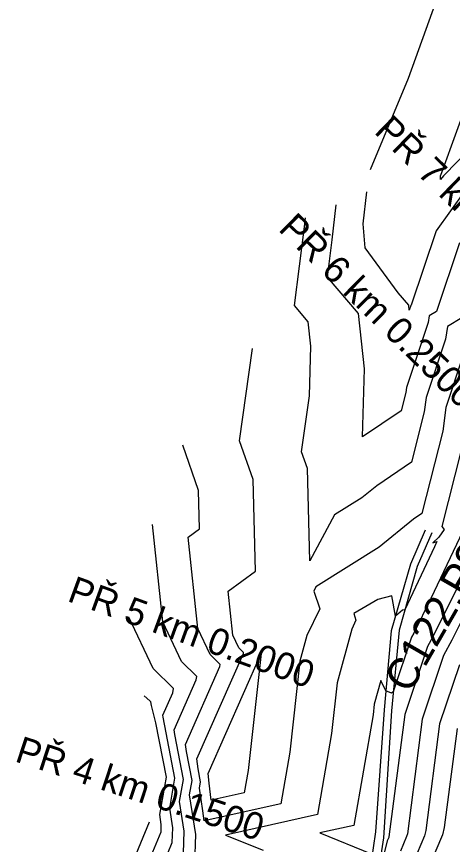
# Model space of a CAD drawing. Extents: x -549394 to -546608, y -1037055 to -1033629.
# Drawn here: x -548903.2 to -548756.1, y -1034201.2 to -1033921.5 of the extents above; entities that cross this region are included whole.
import ezdxf

# ---------------------------------------------------------------- set-up
doc = ezdxf.new("R2010")
doc.units = 0
for name, color, linetype in [('hlavni_vrst', 7, 'Continuous'), ('hrana_L', 7, 'Continuous'), ('norm_vrst', 7, 'Continuous'), ('x_popis_pricne_rezy_C122', 7, 'Continuous'), ('x_popis_velky_C122', 7, 'Continuous')]:
    doc.layers.add(name, color=color, linetype=linetype)

msp = doc.modelspace()

# ---------------------------------------------------------------- linework, layer by layer
at = {"layer": 'hlavni_vrst'}
for p, q in [((-548827.91, -1034064.82), (-548823.56, -1034033.65)), ((-548752.53, -1034036.21), (-548758.32, -1034053.57)), ((-548758.32, -1034053.57), (-548759.35, -1034061.54)), ((-548759.35, -1034061.54), (-548766.36, -1034089.43)), ((-548823.39, -1034077.91), (-548827.91, -1034064.82)), ((-548822.61, -1034108.85), (-548823.39, -1034077.91)), ((-548766.36, -1034089.43), (-548769.21, -1034091.35)), ((-548769.21, -1034091.35), (-548780.77, -1034100.82)), ((-548780.77, -1034100.82), (-548802.13, -1034114.16)), ((-548831.8, -1034115.63), (-548822.61, -1034108.85)), ((-548802.13, -1034114.16), (-548802.91, -1034115.6)), ((-548830.24, -1034130.51), (-548831.8, -1034115.63)), ((-548802.91, -1034115.6), (-548800.87, -1034121.57)), ((-548800.87, -1034121.57), (-548805.2, -1034130.59)), ((-548828.23, -1034134.75), (-548830.24, -1034130.51)), ((-548805.2, -1034130.59), (-548807.58, -1034139.32)), ((-548842.4, -1034172.34), (-548826.65, -1034136.72)), ((-548826.6, -1034136.36), (-548828.23, -1034134.75)), ((-548826.65, -1034136.72), (-548826.6, -1034136.36)), ((-548807.58, -1034139.32), (-548810.97, -1034169.99)), ((-548753.73, -1034140.48), (-548760.4, -1034160.49)), ((-548760.4, -1034160.49), (-548765.06, -1034196.56)), ((-548810.97, -1034169.99), (-548813.99, -1034187.47)), ((-548841.96, -1034175.65), (-548842.4, -1034172.34)), ((-548841.11, -1034180.08), (-548841.96, -1034175.65)), ((-548841.49, -1034182.24), (-548841.11, -1034180.08)), ((-548840.29, -1034189.9), (-548841.49, -1034182.24)), ((-548813.99, -1034187.47), (-548839.92, -1034193.24)), ((-548839.92, -1034193.24), (-548840.29, -1034189.9)), ((-548866.32, -1034212.87), (-548858.35, -1034193.59)), ((-548765.47, -1034198.27), (-548769.17, -1034207.05)), ((-548765.06, -1034196.56), (-548765.47, -1034198.27))]:
    msp.add_line(p, q, dxfattribs=at)
at = {"layer": 'hrana_L'}
for p, q in [((-548765.24, -1034094.98), (-548770.17, -1034106.46)), ((-548763, -1034095.87), (-548768.02, -1034107.25)), ((-548770.17, -1034106.46), (-548776.76, -1034129.09)), ((-548768.02, -1034107.25), (-548774.07, -1034128.86)), ((-548776.76, -1034129.09), (-548779.07, -1034155.75)), ((-548774.07, -1034128.86), (-548776.65, -1034156.06)), ((-548779.07, -1034155.75), (-548782.05, -1034196.95)), ((-548776.65, -1034156.06), (-548779.39, -1034199)), ((-548782.05, -1034196.95), (-548784.21, -1034211.37)), ((-548779.39, -1034199), (-548781.43, -1034212.74))]:
    msp.add_line(p, q, dxfattribs=at)
at = {"layer": 'norm_vrst'}
for p, q in [((-548770.93, -1033942.25), (-548761.43, -1033916.07)), ((-548759.67, -1033974.12), (-548741.85, -1033924.97)), ((-548722.73, -1033938.1), (-548759.11, -1033975.23)), ((-548783.78, -1033973.1), (-548770.93, -1033942.25)), ((-548760.14, -1033975.25), (-548759.67, -1033974.12)), ((-548760.04, -1033976.54), (-548760.14, -1033975.25)), ((-548759.11, -1033975.23), (-548760.04, -1033976.54)), ((-548751.9, -1033980.31), (-548761.58, -1033993.91)), ((-548786.2, -1033991.45), (-548785.02, -1033980.7)), ((-548796.62, -1033996.93), (-548795.32, -1033985.1)), ((-548805.97, -1033992.57), (-548805.63, -1033989.5)), ((-548785.58, -1033999.63), (-548786.2, -1033991.45)), ((-548809.39, -1034019.11), (-548805.97, -1033992.57)), ((-548761.58, -1033993.91), (-548770.05, -1034019.02)), ((-548798.24, -1034009.5), (-548796.62, -1033996.93)), ((-548774.44, -1034014.78), (-548785.58, -1033999.63)), ((-548753.63, -1033997.94), (-548761.45, -1034021.12)), ((-548787.78, -1034021.81), (-548798.24, -1034009.5)), ((-548770.82, -1034019.04), (-548774.44, -1034014.78)), ((-548804.74, -1034024.58), (-548809.39, -1034019.11)), ((-548770.64, -1034020.65), (-548770.82, -1034019.04)), ((-548770.13, -1034019.13), (-548770.64, -1034020.65)), ((-548770.12, -1034019.07), (-548770.13, -1034019.13)), ((-548770.05, -1034019.02), (-548770.12, -1034019.07)), ((-548785.7, -1034040.5), (-548787.78, -1034021.81)), ((-548761.45, -1034021.12), (-548763.92, -1034022.61)), ((-548803.82, -1034032.89), (-548804.74, -1034024.58)), ((-548764.27, -1034024.82), (-548771.59, -1034046.78)), ((-548763.92, -1034022.61), (-548764.27, -1034024.82)), ((-548752.84, -1034023.23), (-548757.71, -1034026.15)), ((-548757.71, -1034026.15), (-548758.4, -1034030.52)), ((-548758.4, -1034030.52), (-548764.96, -1034050.17)), ((-548804.34, -1034049.67), (-548803.82, -1034032.89)), ((-548786.42, -1034063.53), (-548785.7, -1034040.5)), ((-548771.59, -1034046.78), (-548771.82, -1034048.54)), ((-548806.98, -1034068.56), (-548804.34, -1034049.67)), ((-548771.82, -1034048.54), (-548773.37, -1034054.73)), ((-548764.96, -1034050.17), (-548765.58, -1034055.04)), ((-548773.37, -1034054.73), (-548786.42, -1034063.53)), ((-548765.58, -1034055.04), (-548769.87, -1034072.08)), ((-548841.76, -1034081.61), (-548847.06, -1034066.26)), ((-548805.03, -1034074.21), (-548806.98, -1034068.56)), ((-548753.11, -1034068.04), (-548759.59, -1034093.8)), ((-548769.87, -1034072.08), (-548781.63, -1034080.02)), ((-548804.23, -1034105.43), (-548805.03, -1034074.21)), ((-548781.63, -1034080.02), (-548786.62, -1034084.1)), ((-548841.43, -1034094.56), (-548841.76, -1034081.61)), ((-548786.62, -1034084.1), (-548795.84, -1034089.86)), ((-548795.84, -1034089.86), (-548804.23, -1034105.43)), ((-548735.41, -1034090.19), (-548756.29, -1034132.24)), ((-548853.84, -1034126.05), (-548857.3, -1034093.07)), ((-548845.27, -1034097.4), (-548841.43, -1034094.56)), ((-548758.88, -1034094.82), (-548760.61, -1034097.41)), ((-548759.59, -1034093.8), (-548758.88, -1034094.82)), ((-548842.04, -1034128.28), (-548845.27, -1034097.4)), ((-548752.55, -1034095.38), (-548763.32, -1034118.11)), ((-548760.62, -1034097.41), (-548762.66, -1034099.32)), ((-548760.62, -1034097.41), (-548760.61, -1034097.41)), ((-548762.09, -1034100.69), (-548772.14, -1034121.96)), ((-548762.66, -1034099.32), (-548761.36, -1034098.81)), ((-548762.66, -1034099.32), (-548762.66, -1034099.32)), ((-548761.36, -1034098.81), (-548762.09, -1034100.69)), ((-548761.36, -1034098.81), (-548761.36, -1034098.81)), ((-548749.37, -1034104.15), (-548762.71, -1034131.02)), ((-548776.52, -1034117.22), (-548781.24, -1034118.42)), ((-548775.31, -1034124.1), (-548776.52, -1034117.22)), ((-548781.24, -1034118.42), (-548789.39, -1034123.23)), ((-548763.32, -1034118.11), (-548769.13, -1034129.8)), ((-548789.39, -1034123.23), (-548788.64, -1034125.44)), ((-548772.89, -1034122.08), (-548775.31, -1034124.1)), ((-548772.14, -1034121.96), (-548772.89, -1034122.08)), ((-548857.15, -1034141.72), (-548865.38, -1034124.38)), ((-548788.64, -1034125.44), (-548790.08, -1034128.44)), ((-548847.51, -1034139.4), (-548853.84, -1034126.05)), ((-548837.87, -1034137.08), (-548842.04, -1034128.28)), ((-548790.08, -1034128.44), (-548795.02, -1034146.56)), ((-548769.92, -1034131.23), (-548776.04, -1034149.6)), ((-548769.13, -1034129.8), (-548769.92, -1034131.23)), ((-548762.71, -1034131.02), (-548764.52, -1034134.32)), ((-548764.52, -1034134.32), (-548772.18, -1034157.28)), ((-548756.29, -1034132.24), (-548759.13, -1034137.4)), ((-548838.59, -1034177.28), (-548820.65, -1034136.68)), ((-548834.48, -1034140.42), (-548837.87, -1034137.08)), ((-548820.65, -1034136.68), (-548825.02, -1034176.26)), ((-548842.37, -1034144.47), (-548847.51, -1034139.4)), ((-548759.13, -1034137.4), (-548766.29, -1034158.88)), ((-548850.26, -1034148.53), (-548857.15, -1034141.72)), ((-548846.21, -1034167.4), (-548834.61, -1034141.15)), ((-548834.61, -1034141.15), (-548834.48, -1034140.42)), ((-548850.02, -1034162.46), (-548842.56, -1034145.59)), ((-548842.56, -1034145.59), (-548842.37, -1034144.47)), ((-548795.02, -1034146.56), (-548796.92, -1034163.72)), ((-548780.28, -1034145.8), (-548782.46, -1034153.8)), ((-548778.51, -1034149.32), (-548780.28, -1034145.8)), ((-548858.19, -1034152.69), (-548860.15, -1034151.05)), ((-548853.82, -1034157.52), (-548850.51, -1034150.02)), ((-548850.51, -1034150.02), (-548850.26, -1034148.53)), ((-548776.67, -1034150.12), (-548778.51, -1034149.32)), ((-548776.04, -1034149.6), (-548776.67, -1034150.12)), ((-548858.19, -1034152.69), (-548857.94, -1034153.02)), ((-548857.7, -1034154.26), (-548857.94, -1034153.02)), ((-548782.46, -1034153.8), (-548782.86, -1034157.44)), ((-548856.17, -1034160.15), (-548857.7, -1034154.26)), ((-548853.73, -1034158.22), (-548853.82, -1034157.52)), ((-548849.76, -1034178.87), (-548853.73, -1034158.22)), ((-548782.86, -1034157.44), (-548789.33, -1034194.79)), ((-548772.18, -1034157.28), (-548777.52, -1034198.68)), ((-548766.29, -1034158.88), (-548771.29, -1034197.62)), ((-548852.64, -1034178.46), (-548856.17, -1034160.15)), ((-548754.51, -1034162.09), (-548758.83, -1034195.5)), ((-548849.81, -1034164.03), (-548850.02, -1034162.46)), ((-548846.87, -1034179.27), (-548849.81, -1034164.03)), ((-548796.92, -1034163.72), (-548801.66, -1034191.13)), ((-548845.88, -1034169.84), (-548846.21, -1034167.4)), ((-548843.99, -1034179.67), (-548845.88, -1034169.84)), ((-548825.02, -1034176.26), (-548826.33, -1034183.81)), ((-548854.88, -1034191.15), (-548852.64, -1034178.46)), ((-548851.53, -1034188.92), (-548849.76, -1034178.87)), ((-548838.16, -1034180.53), (-548838.59, -1034177.28)), ((-548848.19, -1034186.7), (-548846.87, -1034179.27)), ((-548844.84, -1034184.47), (-548843.99, -1034179.67)), ((-548837.52, -1034186.3), (-548838.16, -1034180.53)), ((-548842.74, -1034197.92), (-548844.84, -1034184.47)), ((-548826.33, -1034183.81), (-548837.52, -1034186.3)), ((-548846.61, -1034196.78), (-548848.19, -1034186.7)), ((-548850.49, -1034195.63), (-548851.53, -1034188.92)), ((-548854.36, -1034194.49), (-548854.88, -1034191.15)), ((-548801.66, -1034191.13), (-548832.73, -1034198.05)), ((-548854.44, -1034196.95), (-548854.36, -1034194.49)), ((-548850.64, -1034200.57), (-548850.49, -1034195.63)), ((-548789.33, -1034194.79), (-548800.85, -1034197.36)), ((-548758.83, -1034195.5), (-548759.42, -1034197.95)), ((-548860.59, -1034211.8), (-548854.44, -1034196.95)), ((-548846.84, -1034204.2), (-548846.61, -1034196.78)), ((-548843.05, -1034207.82), (-548842.74, -1034197.92)), ((-548832.73, -1034198.05), (-548819.92, -1034203.21)), ((-548800.85, -1034197.36), (-548783.18, -1034204.48)), ((-548777.52, -1034198.68), (-548777.57, -1034198.9)), ((-548771.52, -1034198.59), (-548773.61, -1034203.55)), ((-548771.29, -1034197.62), (-548771.52, -1034198.59)), ((-548759.42, -1034197.95), (-548764.73, -1034210.55)), ((-548854.85, -1034210.74), (-548850.64, -1034200.57)), ((-548778.06, -1034200.05), (-548781.29, -1034212.82)), ((-548777.57, -1034198.9), (-548778.06, -1034200.05))]:
    msp.add_line(p, q, dxfattribs=at)

# ---------------------------------------------------------------- texts
at = {"layer": 'x_popis_pricne_rezy_C122'}
for s, rotation, p in [('PŘ 7 km 0.3000', 315.9523, (-548782.83, -1033960.62)), ('PŘ 6 km 0.2500', 315.5825, (-548815.16, -1033993.6)), ('PŘ 5 km 0.2000', 340.0029, (-548886.47, -1034118.87)), ('PŘ 4 km 0.1500', 341.8627, (-548904.17, -1034173.08))]:
    msp.add_text(s, height=9.0627, rotation=rotation, dxfattribs=at).set_placement(p)
at = {"layer": 'x_popis_velky_C122'}
msp.add_text('C122,P3/20', height=10.5, rotation=60.1062, dxfattribs=at).set_placement((-548770.49, -1034150.57))

doc.saveas('drawing.dxf')
